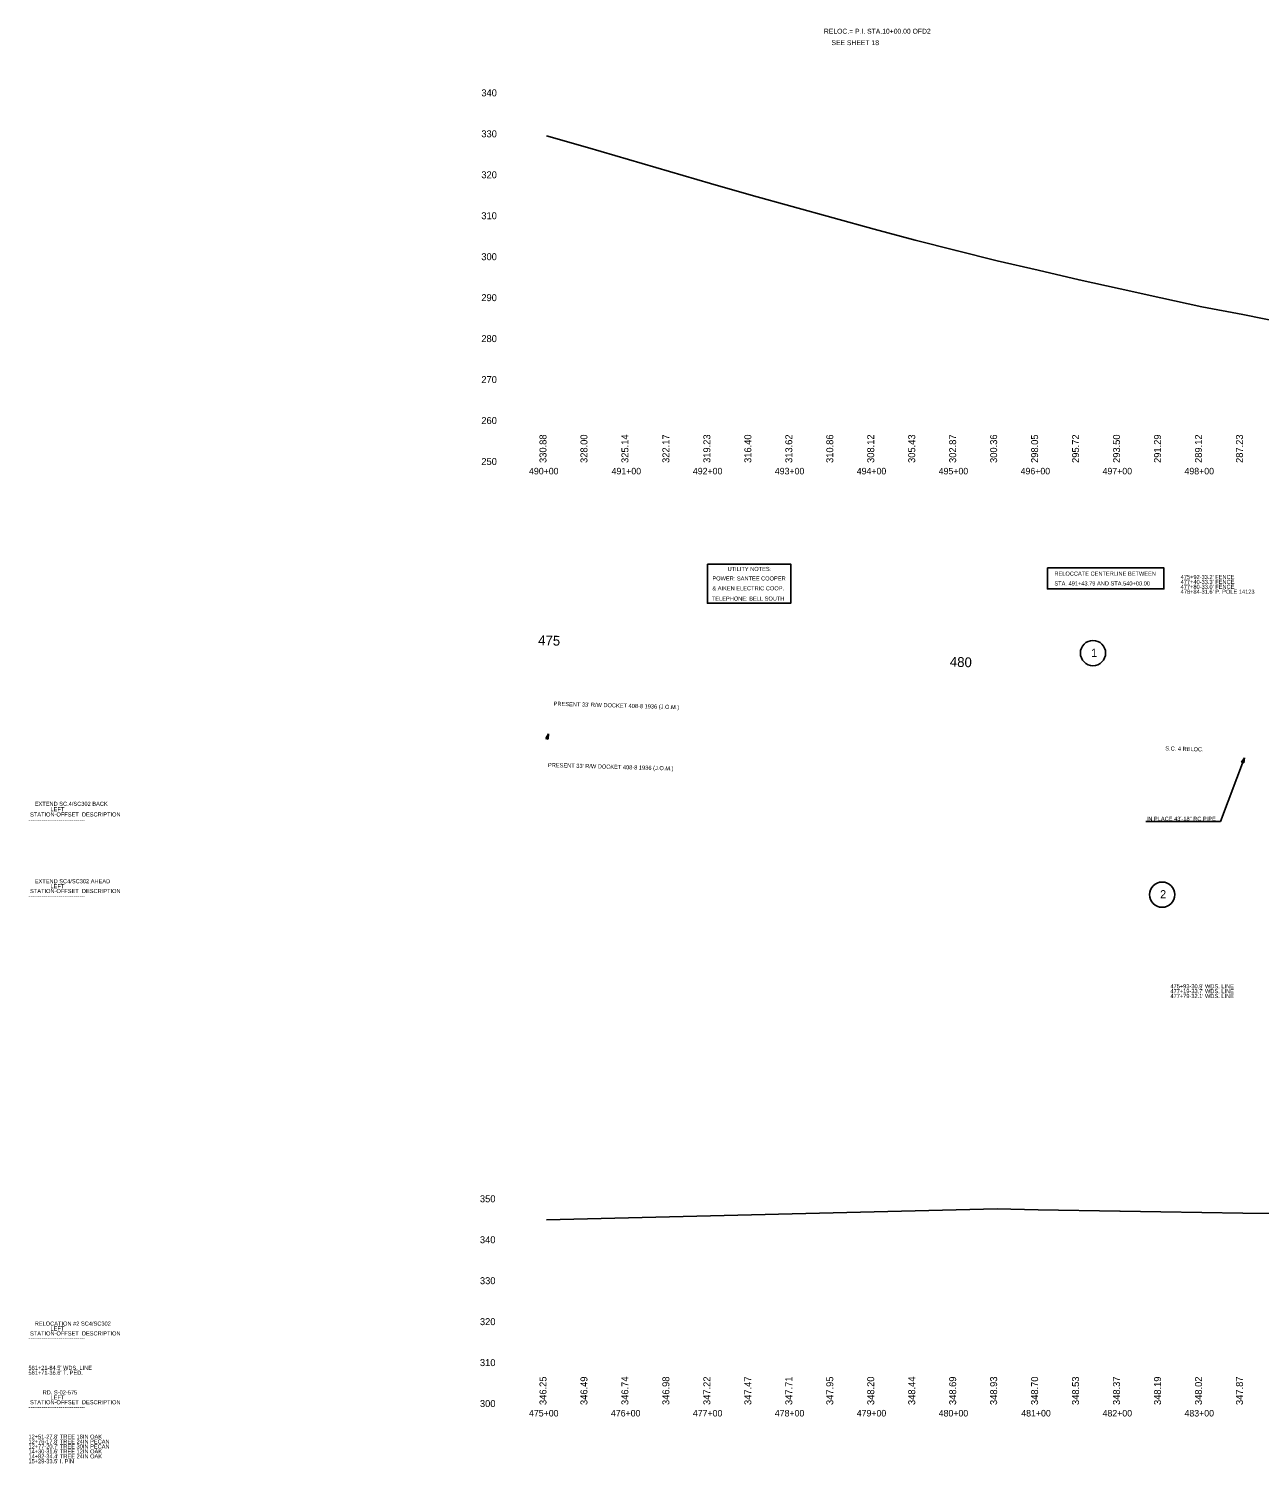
# Model space of a CAD drawing. Extents: x 48556 to 51363, y 45290 to 53458.
# Drawn here: x 48556 to 50058, y 45457 to 47208 of the extents above; entities that cross this region are included whole.
import ezdxf

# ---------------------------------------------------------------- set-up
doc = ezdxf.new("R2010")
doc.units = 0
for name, color, linetype in [('Level 1', 7, 'Continuous'), ('Level 12', 7, 'Continuous'), ('Level 19', 7, 'Continuous'), ('Level 24', 7, 'Continuous'), ('Level 39', 7, 'Continuous'), ('Level 40', 7, 'Continuous'), ('Level 42', 7, 'Continuous'), ('Level 43', 7, 'Continuous'), ('Level 6', 7, 'Continuous')]:
    doc.layers.add(name, color=color, linetype=linetype)

msp = doc.modelspace()

# ---------------------------------------------------------------- linework, layer by layer
at = {"layer": 'Level 12'}
for centre in [(49854.9, 46445.8), (49939.3, 46150.9)]:
    msp.add_circle(centre, 15.4, dxfattribs=at)
at = {"layer": 'Level 24'}
for p, q in [((49190.4, 46347.1), (49187.3, 46341.7)), ((49190.4, 46347.1), (49187.3, 46341.7)), ((49187.3, 46341.7), (49190.1, 46340.9)), ((49187.3, 46341.7), (49190.1, 46340.9)), ((49190.1, 46340.9), (49190.4, 46347.1)), ((49190.1, 46340.9), (49190.4, 46347.1)), ((50039.7, 46317.8), (50036.2, 46312.7)), ((50036.2, 46312.7), (50039, 46311.7)), ((50039, 46311.7), (50039.7, 46317.8))]:
    msp.add_line(p, q, dxfattribs=at)
at = {"layer": 'Level 40'}
for points in [[(49187.9, 47077.2), (49237.9, 47062.8), (49287.9, 47048.5), (49337.9, 47033.7), (49387.9, 47019), (49437.9, 47004.8), (49487.9, 46990.9), (49537.9, 46977.2), (49587.9, 46963.4), (49637.9, 46950), (49687.9, 46937.2), (49737.9, 46924.6), (49787.9, 46913.1), (49837.9, 46901.4), (49887.9, 46890.4), (49937.9, 46879.3), (49987.9, 46868.5), (50037.9, 46859), (50087.9, 46848.8)], [(49187.9, 45754.1), (49737.9, 45767.5), (49787.9, 45766.3), (49787.9, 45766.3), (49887.7, 45764.7), (49887.9, 45764.7), (49937.9, 45763.8), (49987.9, 45762.9), (50037.9, 45762.2), (50087.9, 45761.7), (50137.9, 45760.9), (50187.9, 45760.1), (50237.9, 45758.5), (50287.9, 45755.6), (50337.9, 45751.3), (50387.9, 45745.5), (50437.9, 45738.1), (50487.9, 45728.7), (50537.9, 45717.2), (50587.9, 45704.4), (50637.9, 45691.2), (50687.9, 45677.2)]]:
    msp.add_lwpolyline(points, dxfattribs=at)
at = {"layer": 'Level 6'}
for p, q in [((50039.7, 46317.8), (50010.4, 46240)), ((50010.4, 46240), (49919.4, 46240))]:
    msp.add_line(p, q, dxfattribs=at)
for points in [[(49384.3, 46554.4), (49486.1, 46554.4), (49486.1, 46506.6), (49384.3, 46506.6)], [(49799.3, 46549.8), (49941.4, 46549.8), (49941.4, 46524.1), (49799.3, 46524.1)]]:
    msp.add_lwpolyline(points, close=True, dxfattribs=at)

# ---------------------------------------------------------------- texts
at = {"layer": 'Level 1'}
for s, p in [('RELOC.= P.I. STA.10+00.00 OFD2', (49526.5, 47201.9)), ('    SEE SHEET 18', (49526.5, 47187.9))]:
    msp.add_text(s, height=6, dxfattribs=at).set_placement(p)
for p in [(49196.6, 46381.5), (49189.7, 46306.7)]:
    msp.add_text("PRESENT 33' R/W DOCKET 408-8 1936 (J.O.M.)", height=5, rotation=358.4044, dxfattribs=at).set_placement(p)
at = {"layer": 'Level 12'}
for s, p in [('1', (49852.6, 46441.1)), ('2', (49936.8, 46146.4))]:
    msp.add_text(s, height=10, dxfattribs=at).set_placement(p)
at = {"layer": 'Level 19'}
for s, p in [('475', (49177.7, 46455.5)), ('480', (49680.1, 46429.2))]:
    msp.add_text(s, height=12, rotation=358.3796, dxfattribs=at).set_placement(p)
at = {"layer": 'Level 24'}
for s, p in [("475+92-33.2' FENCE", (49961.9, 46536.2)), ("477+40-33.3' FENCE", (49961.9, 46530.2)), ("477+80-33.0' FENCE", (49961.9, 46524.2)), ("478+84-31.6' P. POLE 14123", (49961.9, 46518.2)), (' STATION-OFFSET  DESCRIPTION', (48555.7, 46246.3)), ('    EXTEND SC.4/SC302 BACK    ', (48555.7, 46259.3)), ('              LEFT            ', (48555.7, 46252.8)), ('------------------------------', (48555.7, 46239.8)), ('    EXTEND SC4/SC302 AHEAD    ', (48555.7, 46164.8)), ('              LEFT            ', (48555.7, 46158.8)), ('------------------------------', (48555.7, 46146.8)), (' STATION-OFFSET  DESCRIPTION', (48555.7, 46152.8)), ("475+93-30.9' WDS. LINE", (49949.4, 46036.6)), ("477+19-33.7' WDS. LINE", (49949.4, 46030.6)), ("477+79-32.1' WDS. LINE", (49949.4, 46024.6)), ('    RELOCATION #2 SC4/SC302   ', (48555.7, 45624.8)), ('              LEFT            ', (48555.7, 45618.8)), ('------------------------------', (48555.7, 45606.8)), (' STATION-OFFSET  DESCRIPTION', (48555.7, 45612.8)), ("561+21-84.5' WDS. LINE", (48555.7, 45570.8)), ("561+71-36.6' T. PED.", (48555.7, 45564.8)), (' STATION-OFFSET  DESCRIPTION', (48555.7, 45528.8)), ('         RD. S-02-575         ', (48555.7, 45540.8)), ('              LEFT            ', (48555.7, 45534.8)), ('------------------------------', (48555.7, 45522.8)), ("12+51-27.8' TREE 18IN OAK", (48555.7, 45486.8)), ("12+76-17.8' TREE 24IN PECAN", (48555.7, 45480.8)), ("12+77-20.7' TREE 30IN PECAN", (48555.7, 45474.8)), ("14+30-31.6' TREE 12IN OAK", (48555.7, 45468.8)), ("14+82-34.4' TREE 24IN OAK", (48555.7, 45462.8)), ("15+29-33.5' I. PIN", (48555.7, 45456.8))]:
    msp.add_text(s, height=5, dxfattribs=at).set_placement(p)
at = {"layer": 'Level 39'}
msp.add_text('S.C. 4 RELOC.', height=5, rotation=358.3796, dxfattribs=at).set_placement((49943.1, 46327))
at = {"layer": 'Level 42'}
for s, height, p in [('340', 8.5, (49108.4, 47125.4)), ('330', 8.5, (49108.4, 47075.4)), ('320', 8.5, (49108.4, 47025.4)), ('310', 8.5, (49108.4, 46975.4)), ('300', 8.5, (49108.4, 46925.4)), ('290', 8.5, (49108.4, 46875.4)), ('280', 8.5, (49108.4, 46825.4)), ('270', 8.5, (49108.4, 46775.4)), ('260', 8.5, (49108.4, 46725.4)), ('250', 8.5, (49108.4, 46675.4)), ('490+00', 8, (49166.6, 46663.9)), ('491+00', 8, (49267.4, 46663.9)), ('492+00', 8, (49366.6, 46663.9)), ('493+00', 8, (49466.6, 46663.9)), ('494+00', 8, (49566.6, 46663.9)), ('495+00', 8, (49666.6, 46663.9)), ('496+00', 8, (49766.6, 46663.9)), ('497+00', 8, (49866.6, 46663.9)), ('498+00', 8, (49966.6, 46663.9)), ('350', 8.5, (49106.7, 45775.4)), ('340', 8.5, (49106.7, 45725.4)), ('330', 8.5, (49106.7, 45675.4)), ('320', 8.5, (49106.7, 45625.4)), ('310', 8.5, (49106.7, 45575.4)), ('300', 8.5, (49106.7, 45525.4)), ('475+00', 8, (49166.6, 45513.9)), ('476+00', 8, (49266.6, 45513.9)), ('477+00', 8, (49366.6, 45513.9)), ('478+00', 8, (49466.6, 45513.9)), ('479+00', 8, (49566.6, 45513.9)), ('480+00', 8, (49666.6, 45513.9)), ('481+00', 8, (49767.4, 45513.9)), ('482+00', 8, (49866.6, 45513.9)), ('483+00', 8, (49966.6, 45513.9))]:
    msp.add_text(s, height=height, dxfattribs=at).set_placement(p)
at = {"layer": 'Level 43'}
for s, p in [('330.88', (49187.9, 46677.9)), ('328.00', (49237.9, 46677.9)), ('325.14', (49287.9, 46677.9)), ('322.17', (49337.9, 46677.9)), ('319.23', (49387.9, 46677.9)), ('316.40', (49437.9, 46677.9)), ('313.62', (49487.9, 46677.9)), ('310.86', (49537.9, 46677.9)), ('308.12', (49587.9, 46677.9)), ('305.43', (49637.9, 46677.9)), ('302.87', (49687.9, 46677.9)), ('300.36', (49737.9, 46677.9)), ('298.05', (49787.9, 46677.9)), ('295.72', (49837.9, 46677.9)), ('293.50', (49887.9, 46677.9)), ('291.29', (49937.9, 46677.9)), ('289.12', (49987.9, 46677.9)), ('287.23', (50037.9, 46677.9)), ('346.25', (49187.9, 45527.9)), ('346.49', (49237.9, 45527.9)), ('346.74', (49287.9, 45527.9)), ('346.98', (49337.9, 45527.9)), ('347.22', (49387.9, 45527.9)), ('347.47', (49437.9, 45527.9)), ('347.71', (49487.9, 45527.9)), ('347.95', (49537.9, 45527.9)), ('348.20', (49587.9, 45527.9)), ('348.44', (49637.9, 45527.9)), ('348.69', (49687.9, 45527.9)), ('348.93', (49737.9, 45527.9)), ('348.70', (49787.9, 45527.9)), ('348.53', (49837.9, 45527.9)), ('348.37', (49887.9, 45527.9)), ('348.19', (49937.9, 45527.9)), ('348.02', (49987.9, 45527.9)), ('347.87', (50037.9, 45527.9))]:
    msp.add_text(s, height=8.5, rotation=90, dxfattribs=at).set_placement(p)
at = {"layer": 'Level 6'}
for s, p in [('UTILITY NOTES:', (49408.9, 46546)), ('POWER: SANTEE COOPER ', (49390.4, 46534.4)), ('STA. 491+43.79 AND STA.540+00.00', (49807.8, 46528.3)), ('RELOCCATE CENTERLINE BETWEEN', (49807.8, 46540.3)), ('TELEPHONE: BELL SOUTH', (49389.7, 46509.8)), ('& AIKEN ELECTRIC COOP.', (49390.4, 46522.4)), ('IN PLACE 43\'-18" RC PIPE', (49920.5, 46241))]:
    msp.add_text(s, height=5, dxfattribs=at).set_placement(p)

doc.saveas('drawing.dxf')
